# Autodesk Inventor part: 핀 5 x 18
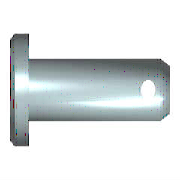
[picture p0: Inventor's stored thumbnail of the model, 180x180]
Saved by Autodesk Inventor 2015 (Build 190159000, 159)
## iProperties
Created: 2012-02
Part Number: 핀 5 x 18
Material: 강철
Description: 머리가 있는 클레비스 핀
Document SubType Name: Modeling
Standard: ISO 2341
Designer: test
Standard Revision: Second edition 1986-11-01
Standards Organization: ISO
Language: ko-KR
Size Designation: B - 5 x 18
Categories: <MemberInstance><Categories><Category DisplayName="조임쇠" InternalName="e4da775c-781d-43d5-af7c-5136215cf5a6" Mnemonic="FSTN"><Category DisplayName="핀" InternalNa
Density: 7.85 g/cm^3
Appearance: 강철
IsCustomPart: 1
Author: test
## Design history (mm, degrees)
sketch "스케치1"
  geometry: L1 (-1.6, 0)-(-1.6, 4); L2 (-1.6, 4)-(0, 4); L3 (0, 4)-(0, 2.5); L4 (0, 2.5)-(18, 2.5); L5 (18, 2.5)-(18, 0); L6 (-1.6, 0)-(18, 0); L7 (-4, 0)-(17, 0) reference; L8 (0, -0.98)-(0, 3.08) reference; C1 r 0.6 at (15.1, 0)
  constraints: 12 end point, 3 parallel, 2 collinear, 2 perpendicular, 1 centre point, 1 point on line, 1 vertical
  dimensions: "d0" = 5 diameter of L4 L6 (= NND); "d1" = 8 diameter of L2 L6 (= KOD); "d2" = 1.6 distance of L1.end L2.end (= KOH); "d3" = 18 distance of L3.end L4.end (= NLG); "d5" = 2.9 distance from line of L5 C1.centre (= DIST); "d6" = 1.2 diameter of C1 (= BOR)
revolve "본체" stored, may be unused: angle "d4" = 90 deg
extrude "구멍" cut sketch "스케치1" stored distance "d7" = 5 (= NND); taper "d8" = 0 deg
workaxis "Work Axis1"
workplane "Work Plane1"
body "Solid1"
chamfer "모따기1" distance "d9" = 1 (= PHH2); stored, may be unused: angle "d10" = 45 deg (= FAWI2), second distance "d16" = 1 (= PHH2)
chamfer "모따기2" distance "d11" = 2 (= PHH1); stored, may be unused: angle "d12" = 30 deg (= FAWI1), second distance "d17" = 2 (= PHH1)
other parameters: "PHH1" = 2 [user parameter; used in 2 equation terms], "PHH2" = 1 [user parameter; used in 2 equation terms], "KOD" = 8 [user parameter; used in 1 equation term], "KOH" = 1.6 [user parameter; used in 1 equation term], "NND" = 5 [user parameter; used in 2 equation terms], "FAWI1" = 30 deg [user parameter; used in 1 equation term], "FAWI2" = 45 deg [user parameter; used in 1 equation term], "DIST" = 2.9 [user parameter; used in 1 equation term], "BOR" = 1.2 [user parameter; used in 1 equation term], "NLG" = 18 [user parameter; used in 1 equation term], "d13" = 0, "d14" = 0, "d27" = 0, "d28" = 0, "d29" = 0, "d30" = 0, "d31" = 0
